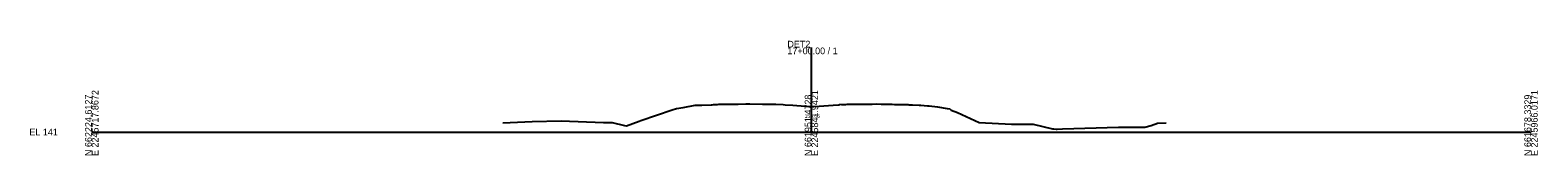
# Model space of a CAD drawing. Extents: x -26 to 603, y -10 to 9526.
# Drawn here: x -26 to 603, y -10 to 38 of the extents above; entities that cross this region are included whole.
import ezdxf

# ---------------------------------------------------------------- set-up
doc = ezdxf.new("R2010")
doc.units = 0
for name, color, linetype in [('Default', 7, 'Continuous'), ('Exist Cross Section Cell', 7, 'Continuous'), ('Exist XS Center Line Elevation Label', 7, 'Continuous'), ('Exist XS Ground Line', 7, 'Continuous')]:
    doc.layers.add(name, color=color, linetype=linetype)

msp = doc.modelspace()

# ---------------------------------------------------------------- linework, layer by layer
at = {"layer": 'Exist Cross Section Cell'}
for p, q in [((300, 0), (300, 35.25)), ((0, 0), (300, 0)), ((300, 0), (600, 0))]:
    msp.add_line(p, q, dxfattribs=at)
at = {"layer": 'Exist XS Ground Line'}
for p, q in [((228.95, 4.77), (241.99, 9.21)), ((241.99, 9.21), (243.79, 9.82)), ((243.79, 9.82), (246.49, 10.26)), ((246.49, 10.26), (251.55, 11.22)), ((251.55, 11.22), (252.63, 11.24)), ((252.63, 11.24), (253.46, 11.21)), ((253.46, 11.21), (254.33, 11.24)), ((254.33, 11.24), (258.24, 11.38)), ((258.24, 11.38), (258.67, 11.41)), ((258.67, 11.41), (259.23, 11.53)), ((259.23, 11.53), (259.8, 11.47)), ((259.8, 11.47), (260.17, 11.49)), ((260.17, 11.49), (260.8, 11.52)), ((260.8, 11.52), (261.34, 11.57)), ((261.34, 11.57), (262.41, 11.58)), ((262.41, 11.58), (263.18, 11.59)), ((263.18, 11.59), (265.66, 11.64)), ((265.66, 11.64), (268.67, 11.68)), ((268.67, 11.68), (269.44, 11.7)), ((269.44, 11.7), (272.69, 11.74)), ((272.69, 11.74), (273.49, 11.75)), ((273.49, 11.75), (274.38, 11.74)), ((274.38, 11.74), (279.65, 11.66)), ((279.65, 11.66), (280.83, 11.65)), ((280.83, 11.65), (283.2, 11.6)), ((283.2, 11.6), (284.45, 11.59)), ((284.45, 11.59), (284.8, 11.59)), ((284.8, 11.59), (285.23, 11.57)), ((285.23, 11.57), (288.23, 11.43)), ((288.23, 11.43), (289.07, 11.36)), ((289.07, 11.36), (292.19, 11.22)), ((292.19, 11.22), (297.4, 10.85)), ((297.4, 10.85), (298.1, 10.8)), ((298.1, 10.8), (300, 10.66)), ((300, 10.66), (300.34, 10.64)), ((300.34, 10.64), (301.03, 10.68)), ((301.03, 10.68), (303.23, 10.83)), ((303.23, 10.83), (309.13, 11.2)), ((309.13, 11.2), (311.7, 11.36)), ((311.7, 11.36), (311.71, 11.58)), ((311.71, 11.58), (312.6, 11.55)), ((312.6, 11.55), (314.29, 11.52)), ((314.29, 11.52), (314.87, 11.59)), ((314.87, 11.59), (315.57, 11.6)), ((315.57, 11.6), (316.11, 11.57)), ((316.11, 11.57), (318.09, 11.6)), ((318.09, 11.6), (318.53, 11.6)), ((318.53, 11.6), (319.48, 11.61)), ((319.48, 11.61), (322.3, 11.64)), ((322.3, 11.64), (323.58, 11.65)), ((323.58, 11.65), (325.32, 11.68)), ((325.32, 11.68), (327, 11.75)), ((327, 11.75), (329.08, 11.66)), ((329.08, 11.66), (331.57, 11.61)), ((331.57, 11.61), (333.63, 11.57)), ((333.63, 11.57), (334.57, 11.56)), ((334.57, 11.56), (337.41, 11.5)), ((337.41, 11.5), (338.75, 11.48)), ((338.75, 11.48), (339.18, 11.48)), ((339.18, 11.48), (340.36, 11.43)), ((340.36, 11.43), (340.78, 11.39)), ((340.78, 11.39), (341.41, 11.41)), ((341.41, 11.41), (341.53, 11.37)), ((341.53, 11.37), (342.13, 11.32)), ((342.13, 11.32), (344.96, 11.17)), ((344.96, 11.17), (345.55, 11.15)), ((345.55, 11.15), (348.38, 11)), ((348.38, 11), (349.06, 10.91)), ((349.06, 10.91), (352.63, 10.54)), ((352.63, 10.54), (356.58, 9.76)), ((356.58, 9.76), (357.77, 9.72)), ((357.77, 9.72), (358.33, 9.11)), ((358.33, 9.11), (360.91, 8.13)), ((360.91, 8.13), (369.87, 4.04)), ((171.36, 3.83), (183.56, 4.46)), ((183.56, 4.46), (195.74, 4.74)), ((195.74, 4.74), (213.28, 3.95)), ((213.28, 3.95), (216.88, 4.04)), ((216.88, 4.04), (222.04, 2.79)), ((222.04, 2.79), (222.92, 2.62)), ((222.92, 2.62), (228.15, 4.52)), ((228.15, 4.52), (228.95, 4.77)), ((369.87, 4.04), (383.36, 3.29)), ((383.36, 3.29), (392.42, 3.31)), ((392.42, 3.31), (400.57, 1.4)), ((400.57, 1.4), (401.07, 1.31)), ((401.07, 1.31), (402.1, 1.22)), ((402.1, 1.22), (402.45, 1.23)), ((402.45, 1.23), (404.7, 1.31)), ((404.7, 1.31), (428, 1.98)), ((428, 1.98), (439.05, 1.98)), ((439.05, 1.98), (441.62, 2.68)), ((441.62, 2.68), (444.33, 3.76)), ((444.33, 3.76), (447.93, 3.82))]:
    msp.add_line(p, q, dxfattribs=at)

# ---------------------------------------------------------------- texts
at = {"layer": 'Default'}
msp.add_text('-', height=0.0001, dxfattribs=at).set_placement((0, 0))
msp.add_text('-', height=0.0001, dxfattribs=at).set_placement((0, 0))
at = {"layer": 'Exist Cross Section Cell'}
for s, p in [('DET2', (290, 35.25)), ('17+00.00 / 1', (290, 32.45)), ('EL 141', (-26, -1.4))]:
    msp.add_text(s, height=2.8, dxfattribs=at).set_placement(p)
for s, p in [('N 662224.6127', (0, -10)), ('E 2245717.8672', (2.8, -10)), ('N 661951.4728', (300, -10)), ('E 2245841.9421', (302.8, -10)), ('N 661678.3329', (600, -10)), ('E 2245966.0171', (602.8, -10))]:
    msp.add_text(s, height=2.8, rotation=90, dxfattribs=at).set_placement(p)
at = {"layer": 'Exist XS Center Line Elevation Label'}
msp.add_text('151.66', height=1.5, dxfattribs=at).set_placement((297.16, 5.91))

doc.saveas('drawing.dxf')
